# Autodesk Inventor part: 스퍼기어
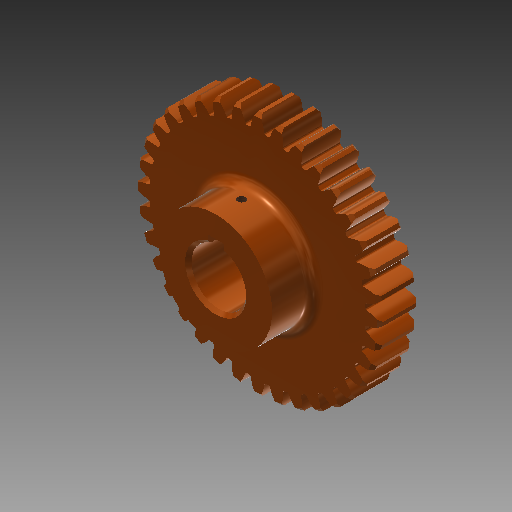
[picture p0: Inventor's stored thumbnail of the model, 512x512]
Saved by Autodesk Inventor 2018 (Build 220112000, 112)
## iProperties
Created: 2019-01
Part Number: 스퍼기어
Material: 알루미늄 6061
Document SubType Name: Modeling
Designer: mduedu
Density: 1 g/cm^3
Appearance: 매끄러움 - 연한 주황색
Author: mduedu
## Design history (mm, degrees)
sketch "스케치1"
  geometry: C1 r 33.5 at (0, 0); 1 further point
  constraints: 1 centre point, 1 coincident
  dimensions: "d0" = 67 diameter of C1
extrude "돌출1" new body sketch "스케치1" stored distance "d2" = 12; taper "d3" = 0 deg
sketch "스케치2" dims "d4" = 72
  geometry: L1 (0, 0)-(-38, 0); L2 (0, 0)-(0, 38); L3 (-0.57, 0)-(-0.57, 37.996); L4 (-1.57, 0)-(-1.57, 37.968); L5 (-2.07, 0)-(-2.07, 37.944); C1 r 33.5 at (0, 0); A1 r 38 centre (0, 0) between (-38, 0) and (0, 38); A2 r 9.246 centre (7.162, 32.926) between (-0.57, 37.996) and (-2.07, 33.436); A3 r 9.246 centre (-7.162, 32.926) between (2.07, 33.436) and (0.57, 37.996); A4 r 33.5 centre (0, 0) between (2.07, 33.436) and (-2.07, 33.436); A5 r 38 centre (0, 0) between (0.57, 37.996) and (-0.57, 37.996); 3 further points
  constraints: 14 point on circle, 10 end point, 6 centre point, 5 coincident, 5 point on line, 3 symmetric about line, 2 parallel, 2 perpendicular, 1 horizontal, 7 other
  dimensions: "d6" = 76 diameter of A1; "d7" = 0.5 distance between parallel lines of L4 L5; "d8" = 1 distance between parallel lines of L3 L4; "d9" = 1.57 distance between parallel lines of L2 L4
extrude "돌출2" join sketch "스케치2" stored distance "d10" = 0; taper "d11" = 0 deg
chamfer "모따기1" distance "d12" = 1; stored, may be unused: second distance "d13" = 2, angle "d14" = 45 deg
fillet "모깎기1" dims "d15" = 0.5
sketch "스케치3"
  geometry: C1 r 17.5 at (0, 0); 1 further point
  constraints: 1 centre point, 1 coincident
  dimensions: "d19" = 35 diameter of C1
extrude "돌출3" join sketch "스케치3" distance "d20" = 13; taper "d21" = 0 deg
sketch "스케치4"
  geometry: L1 (-2.5, 8.124)-(2.5, 8.124); L2 (2.5, 8.124)-(2.5, 10.8); L3 (2.5, 10.8)-(-2.5, 10.8); L4 (-2.5, 10.8)-(-2.5, 8.124); A1 r 8.5 centre (0, 0) between (-2.5, 8.124) and (2.5, 8.124); 1 further point
  constraints: 8 end point, 2 parallel, 2 point on circle, 1 centre point, 1 coincident, 1 horizontal, 1 perpendicular
  dimensions: "d22" = 17 diameter of A1; "d23" = 5 distance of L2.end L3.end; "d24" = 19.3 dimension on A1 L3
extrude "돌출4" cut sketch "스케치4" extent not by distance; stored distance "d25" = 13; taper "d26" = 0 deg
sketch "스케치5"
  geometry: C1 r 15 at (0, 0); C2 r 27.5 at (0, 0); 1 further point
  constraints: 2 centre point, 2 coincident
  dimensions: "d33" = 30 diameter of C1; "d34" = 55 diameter of C2
extrude "돌출5" cut sketch "스케치5" distance "d30" = 6; taper "d31" = 0 deg
fillet "모깎기2" dims "d32" = 3
node "작업 평면1"
sketch "스케치6"
  geometry: L1 (17.5, 13)-(-17.5, 13) reference; 2 further points
  constraints: 1 vertical alignment
  dimensions: "d35" = 8 distance from line of point (0, 5) L1
hole "구멍1" sketch "스케치6" at (0, 5) diameter "d36" = 2.459; stored, may be unused: countersink angle "d40" = 90 deg, drill point angle "d42" = 118 deg; dims "d37" = 6, "d38" = 4, "d39" = 2, "d41" = 8
fillet "모깎기3" dims "d43" = 3
chamfer "모따기2" distance "d44" = 1; stored, may be unused: second distance "d45" = 2, angle "d46" = 45 deg
node "솔리드1"
pattern_circular "원형 패턴1" dims angle "d17" = 360 deg
